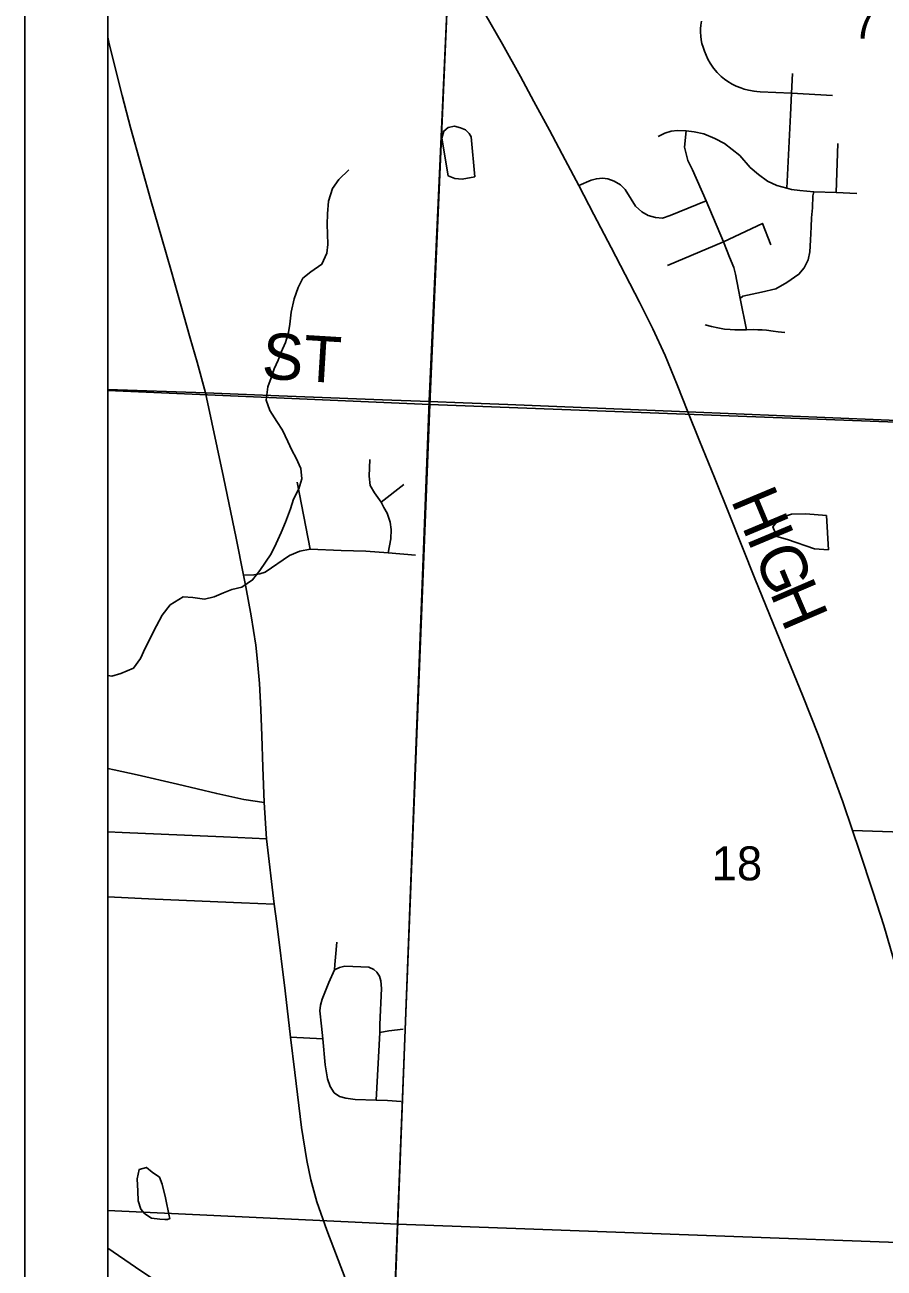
# Model space of a CAD drawing. Extents: x 0 to 34, y 0 to 22.
# Drawn here: x 2.735 to 3.793, y 17.972 to 19.503 of the extents above; entities that cross this region are included whole.
import ezdxf

# ---------------------------------------------------------------- set-up
doc = ezdxf.new("R2010")
doc.units = 0
for name, color, linetype in [('GM_X_Corporation', 7, 'Continuous'), ('GM_X_County_Road', 7, 'Continuous'), ('GM_X_County_Road_Text', 7, 'Continuous'), ('GM_X_Minor_Lake', 7, 'Continuous'), ('GM_X_Minor_River', 7, 'Continuous'), ('GM_X_Section_Text', 7, 'Continuous'), ('GM_X_State_Route', 7, 'Continuous'), ('GM_X_Township_Road', 7, 'Continuous'), ('SH_Data', 7, 'Continuous')]:
    doc.layers.add(name, color=color, linetype=linetype)

msp = doc.modelspace()

# ---------------------------------------------------------------- linework, layer by layer
at = {"layer": 'GM_X_Corporation'}
for points in [[(7.1023, 20.9204), (2.837, 20.9204), (2.837, 14.1204), (9.637, 14.1204), (9.637, 20.9204), (9.4036, 20.9204), (9.4022, 20.8667), (9.2273, 20.8723), (9.1354, 20.8749), (9.124, 20.8753), (8.9858, 20.878), (8.9676, 20.8785), (8.8663, 20.881), (8.6259, 20.8892), (8.5535, 20.8914), (8.5421, 20.8915), (8.4667, 20.8934), (8.0602, 20.9055), (7.9522, 20.9084), (7.1104, 20.9188)], [(3.3169, 20.9204), (2.837, 20.9204), (2.837, 14.9888), (3.0725, 14.9816), (3.0874, 15.351), (3.0879, 15.3623), (3.0883, 15.3712), (3.1072, 15.7483), (3.1177, 16.2414), (3.14, 16.6736), (3.1852, 17.7826), (3.1864, 17.8248), (3.233, 19.0394), (3.2586, 19.6098), (3.2623, 19.6596), (3.2721, 19.8755), (3.2728, 19.892), (3.2744, 19.9301), (3.2774, 20.0014), (3.2794, 20.0412), (3.3026, 20.5526), (3.3089, 20.7046), (3.3168, 20.9187)], [(2.837, 20.0568), (2.837, 19.0523), (3.2335, 19.0353), (3.277, 20.0368)], [(4.3035, 20.0005), (4.2642, 18.9963), (3.2335, 19.0353), (3.277, 20.0368)], [(2.837, 19.0523), (2.837, 18.0425), (3.1939, 18.0257), (3.2335, 19.0353)], [(3.2335, 19.0353), (4.2642, 18.9963), (4.2238, 17.9879), (3.1939, 18.0257)], [(2.837, 18.0425), (2.837, 17.0399), (3.155, 17.0299), (3.1939, 18.0257)], [(3.1939, 18.0257), (4.2238, 17.9879), (4.1823, 16.9818), (3.1533, 17.0117), (3.155, 17.0299)]]:
    msp.add_lwpolyline(points, close=True, dxfattribs=at)
msp.add_lwpolyline([(7.1023, 20.9204), (3.3169, 20.9204), (3.3168, 20.9187), (3.3089, 20.7046), (3.3026, 20.5526), (3.2794, 20.0412), (3.2774, 20.0014), (3.2744, 19.9301), (3.2728, 19.892), (3.2721, 19.8755), (3.2623, 19.6596), (3.2586, 19.6098), (3.233, 19.0394), (3.1864, 17.8248)], dxfattribs=at)
at = {"layer": 'GM_X_County_Road'}
for points in [[(3.8056, 18.3498), (3.7929, 18.3934), (3.7797, 18.4343), (3.7625, 18.4862), (3.7543, 18.5105), (3.7421, 18.5458), (3.7124, 18.6274), (3.6928, 18.6774), (3.6612, 18.7545), (3.6341, 18.8211), (3.6026, 18.8994), (3.5842, 18.9453), (3.5656, 18.9904), (3.5515, 19.0261), (3.5383, 19.0596), (3.5233, 19.0954), (3.5083, 19.1284), (3.4919, 19.1612), (3.4743, 19.1954), (3.4568, 19.2287), (3.4356, 19.2694), (3.4171, 19.305), (3.4004, 19.3367), (3.381, 19.373), (3.3619, 19.4084), (3.3454, 19.4393), (3.3231, 19.4791), (3.3014, 19.5168)], [(2.837, 19.0539), (2.9573, 19.0495), (3.0079, 19.0477), (3.0479, 19.046)], [(3.0479, 19.046), (3.0799, 19.0448), (3.1752, 19.041), (3.2332, 19.0389), (3.2747, 19.0373), (3.3299, 19.0351)], [(3.3299, 19.0351), (3.4202, 19.0314), (3.5515, 19.0261), (4.2655, 18.9966), (4.3563, 18.9933), (4.4885, 18.9883), (4.6568, 18.982), (4.7374, 18.979), (5.2825, 18.9592)]]:
    msp.add_lwpolyline(points, dxfattribs=at)
at = {"layer": 'GM_X_Minor_Lake'}
for points in [[(3.2845, 19.3647), (3.2821, 19.3692), (3.2775, 19.3737), (3.2714, 19.3759), (3.2642, 19.3781), (3.2562, 19.3762), (3.251, 19.3719), (3.2484, 19.3632), (3.2561, 19.3169), (3.2645, 19.3136), (3.2736, 19.3129), (3.2892, 19.3157)], [(3.2892, 19.3157), (3.2845, 19.3647)], [(3.7223, 18.8987), (3.6969, 18.9007), (3.679, 18.9001), (3.6646, 18.8954), (3.656, 18.8847), (3.6611, 18.8726), (3.674, 18.8689), (3.7072, 18.8575), (3.7247, 18.8562)], [(3.7247, 18.8562), (3.7223, 18.8987)], [(3.7223, 18.8987), (3.7246, 18.8562)], [(2.9127, 18.0361), (2.908, 18.0581), (2.9042, 18.0751), (2.9007, 18.0835), (2.8916, 18.0899), (2.8847, 18.0956), (2.8756, 18.0929), (2.8734, 18.0815), (2.8739, 18.0663), (2.8743, 18.0545), (2.8778, 18.0443), (2.8827, 18.0386), (2.8911, 18.0333)], [(2.8911, 18.0333), (2.9013, 18.0318), (2.9073, 18.0313), (2.9104, 18.0315), (2.9134, 18.0327), (2.9127, 18.0361)]]:
    msp.add_lwpolyline(points, dxfattribs=at)
at = {"layer": 'GM_X_Minor_River'}
msp.add_lwpolyline([(3.1341, 19.3243), (3.1217, 19.3124), (3.1138, 19.3013), (3.109, 19.2856), (3.1077, 19.2701), (3.1074, 19.2571), (3.1076, 19.2454), (3.1081, 19.2324), (3.1067, 19.2218), (3.1008, 19.208), (3.0872, 19.1988), (3.0774, 19.1907), (3.0714, 19.1792), (3.0667, 19.1655), (3.063, 19.1491), (3.0613, 19.1343), (3.0595, 19.124), (3.0558, 19.1118), (3.0507, 19.0996), (3.047, 19.0897), (3.0418, 19.079), (3.0381, 19.0679), (3.034, 19.0569), (3.0323, 19.0405), (3.0366, 19.028), (3.0451, 19.0141), (3.0521, 19.0035), (3.0587, 18.9895), (3.0638, 18.9789), (3.0692, 18.9691), (3.075, 18.9566), (3.0759, 18.9437), (3.0723, 18.9315), (3.0659, 18.9185), (3.0619, 18.9067), (3.056, 18.8903), (3.0504, 18.8777), (3.0445, 18.864), (3.0382, 18.8514), (3.0311, 18.841), (3.0243, 18.8307), (3.0154, 18.8192), (3.0022, 18.8103), (2.99, 18.8075), (2.9794, 18.8032), (2.9681, 18.7985), (2.956, 18.7954), (2.9419, 18.7975), (2.9301, 18.7985), (2.9139, 18.7885), (2.9041, 18.7758), (2.897, 18.7628), (2.8829, 18.7353), (2.8773, 18.7223), (2.8687, 18.7105), (2.8532, 18.7038), (2.8419, 18.7007), (2.837, 18.7016)], dxfattribs=at)
at = {"layer": 'GM_X_State_Route'}
msp.add_lwpolyline([(3.1296, 17.9592), (3.1068, 18.0185), (3.0947, 18.0532), (3.0871, 18.0802), (3.0821, 18.1041), (3.0758, 18.1449), (3.0676, 18.2126), (3.0622, 18.2559), (3.0555, 18.3131), (3.0451, 18.3959), (3.0419, 18.42), (3.0326, 18.5002), (3.0297, 18.5449), (3.0281, 18.5887), (3.0268, 18.6273), (3.0255, 18.6595), (3.024, 18.6917), (3.0216, 18.7188), (3.0193, 18.7389), (3.0135, 18.7749), (3.0071, 18.8107), (3.0042, 18.8252), (2.995, 18.8706), (2.9794, 18.9459), (2.9573, 19.0495), (2.9473, 19.0874), (2.9386, 19.1171), (2.9266, 19.1591), (2.9154, 19.1985), (2.9033, 19.2412), (2.8906, 19.2852), (2.8784, 19.3281), (2.865, 19.3765), (2.8549, 19.4157), (2.8389, 19.4794), (2.837, 19.4875)], dxfattribs=at)
at = {"layer": 'GM_X_Township_Road'}
for p, q in [((3.6792, 19.4187), (3.6805, 19.443)), ((3.6777, 19.3919), (3.6792, 19.4187)), ((3.7295, 19.416), (3.6792, 19.4187)), ((3.6734, 19.3015), (3.6777, 19.3919)), ((3.7339, 19.2963), (3.736, 19.3568)), ((3.7066, 19.2973), (3.7339, 19.2963)), ((3.7339, 19.2963), (3.7597, 19.2952)), ((3.0865, 18.8572), (3.0703, 18.9395)), ((3.1739, 18.9151), (3.2018, 18.9367)), ((3.0622, 18.2559), (3.1017, 18.2542))]:
    msp.add_line(p, q, dxfattribs=at)
for points in [[(3.6792, 19.4187), (3.6405, 19.4205), (3.6363, 19.4207), (3.633, 19.4211), (3.626, 19.4224), (3.6209, 19.4238), (3.6168, 19.4252), (3.6108, 19.4275), (3.6062, 19.4299), (3.6007, 19.4331), (3.5964, 19.436), (3.5924, 19.4391), (3.5877, 19.444), (3.583, 19.4496), (3.5788, 19.4557), (3.5762, 19.4606), (3.5739, 19.4654), (3.572, 19.4703), (3.5701, 19.4752), (3.5686, 19.4799), (3.5678, 19.4844), (3.5674, 19.4888), (3.5672, 19.494), (3.5671, 19.4981), (3.5675, 19.5024), (3.5682, 19.5073)], [(3.5148, 19.3655), (3.5229, 19.3696), (3.5307, 19.3719), (3.5385, 19.3729), (3.5492, 19.3721), (3.5591, 19.371), (3.5711, 19.3685), (3.5846, 19.363), (3.5966, 19.3565), (3.6154, 19.342), (3.6282, 19.327), (3.6383, 19.3184), (3.6495, 19.3104), (3.6609, 19.3051), (3.6734, 19.3015)], [(3.6236, 19.1273), (3.616, 19.1658), (3.6102, 19.1957), (3.609, 19.2007), (3.6079, 19.2039), (3.6029, 19.2168), (3.5954, 19.2356), (3.5741, 19.2862), (3.557, 19.3243), (3.5513, 19.3358), (3.5488, 19.3455), (3.5473, 19.3523), (3.5492, 19.3721)], [(3.4171, 19.305), (3.4322, 19.3115), (3.4389, 19.3133), (3.4465, 19.3138), (3.453, 19.313), (3.4605, 19.3103), (3.4685, 19.3058), (3.4743, 19.3), (3.4816, 19.288), (3.4871, 19.2797), (3.4948, 19.2724), (3.5026, 19.2681), (3.5116, 19.2654), (3.5202, 19.2649), (3.5297, 19.2681), (3.5741, 19.2862)], [(3.616, 19.1658), (3.6191, 19.1688), (3.6421, 19.1737), (3.6596, 19.1776), (3.6735, 19.1853), (3.6883, 19.1956), (3.6948, 19.2035), (3.6997, 19.2134), (3.7017, 19.2233), (3.7023, 19.2375), (3.7031, 19.2541), (3.7039, 19.2651), (3.705, 19.2775), (3.7052, 19.2922), (3.7066, 19.2973)], [(3.6734, 19.3015), (3.679, 19.3002), (3.6893, 19.2989), (3.7066, 19.2973)], [(3.5264, 19.2065), (3.5954, 19.2356), (3.6432, 19.2582), (3.6535, 19.2317)], [(3.5728, 19.1333), (3.5806, 19.1312), (3.5884, 19.1295), (3.5964, 19.1282), (3.6037, 19.1275), (3.6092, 19.1271), (3.6161, 19.127), (3.6236, 19.1273), (3.6321, 19.1275), (3.6377, 19.1274), (3.6428, 19.1271), (3.6482, 19.1266), (3.6566, 19.1254), (3.6626, 19.1246), (3.6666, 19.1243), (3.6708, 19.1241)], [(3.1825, 18.8524), (3.1857, 18.8696), (3.1861, 18.8814), (3.1848, 18.8903), (3.181, 18.9014), (3.177, 18.9085), (3.1739, 18.9151), (3.1656, 18.9263), (3.1601, 18.9353), (3.1588, 18.9471), (3.1596, 18.9677)], [(3.0042, 18.8252), (3.0169, 18.8255), (3.0244, 18.8266), (3.031, 18.8288), (3.0608, 18.8491), (3.0734, 18.8546), (3.0865, 18.8572), (3.1244, 18.8553), (3.155, 18.8545), (3.1825, 18.8524), (3.2159, 18.8497)], [(2.837, 18.587), (2.8449, 18.5854), (2.8733, 18.5791), (2.9229, 18.5676), (2.9712, 18.556), (3.0046, 18.5488), (3.0297, 18.5449)], [(2.837, 18.5088), (2.8547, 18.5081), (2.9795, 18.5029), (3.0326, 18.5002)], [(5.2718, 18.4356), (5.2631, 18.4401), (5.2447, 18.4477), (5.2197, 18.4549), (5.194, 18.4582), (5.169, 18.4595), (4.9315, 18.4661), (4.8719, 18.4684), (4.6236, 18.4752), (4.4743, 18.4812), (4.3338, 18.4879), (4.2439, 18.4919), (4.1405, 18.4961), (4.0385, 18.501), (3.8897, 18.5061), (3.7543, 18.5105)], [(3.0419, 18.42), (3.0018, 18.4213), (2.8955, 18.4262), (2.837, 18.429)], [(3.1982, 18.1769), (3.1817, 18.178), (3.1677, 18.1786), (3.1419, 18.1793), (3.1302, 18.181), (3.1223, 18.1831), (3.116, 18.1875), (3.1108, 18.1951), (3.1076, 18.2046), (3.1048, 18.2221), (3.1017, 18.2542), (3.1001, 18.2696), (3.0983, 18.2883), (3.0989, 18.2956), (3.1011, 18.3027), (3.1093, 18.3233), (3.1162, 18.3391), (3.1168, 18.3454), (3.1174, 18.3545), (3.1191, 18.3731)], [(3.1677, 18.1786), (3.172, 18.2619), (3.1723, 18.2716), (3.1742, 18.3161), (3.1735, 18.3253), (3.1716, 18.3311), (3.1684, 18.336), (3.1648, 18.3395), (3.1585, 18.3422), (3.1291, 18.3436), (3.1224, 18.342), (3.1162, 18.3391)], [(3.172, 18.2619), (3.1832, 18.2639), (3.201, 18.2659)], [(3.0003, 17.8855), (2.9774, 17.9017), (2.8713, 17.9729), (2.837, 17.996)]]:
    msp.add_lwpolyline(points, dxfattribs=at)
at = {"layer": 'SH_Data'}
msp.add_line((2.7349, 21.0001), (2.7349, 14.0001), dxfattribs=at)

# ---------------------------------------------------------------- texts
at = {"layer": 'GM_X_County_Road_Text'}
for s, height, rotation, p in [('ST', 0.05682, 356.4993, (3.0259, 19.0673)), ('H', 0.0568, 292.7322, (3.6039, 18.9178)), ('I', 0.0568, 292.7374, (3.6232, 18.8717)), ('G', 0.0568, 292.7418, (3.6322, 18.8501)), ('H', 0.0568, 293.3102, (3.6518, 18.8035))]:
    msp.add_text(s, height=height, rotation=rotation, dxfattribs=at).set_placement(p)
at = {"layer": 'GM_X_Section_Text'}
for s, height, p in [('7', 0.0419, (3.7541, 19.4856)), ('18', 0.04186, (3.5807, 18.4492))]:
    msp.add_text(s, height=height, rotation=0, dxfattribs=at).set_placement(p)

doc.saveas('drawing.dxf')
